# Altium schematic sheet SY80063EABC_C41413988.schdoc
size 127 x 101 mm
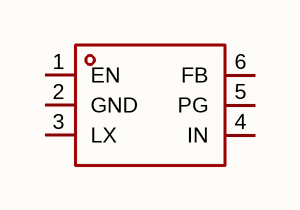
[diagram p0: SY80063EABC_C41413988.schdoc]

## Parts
U?  sy80063eabc_c41413988  [SOT-23-6_L2.9-W1.6-P0.95-LS2.8-BL-1]  (value not drawn)

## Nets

Not connected (* = marked no-connect by the designer): U? 1(EN) 2(GND) 3(LX) 4(IN) 5(PG) 6(FB)

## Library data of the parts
U? = sy80063eabc_c41413988: 功能类型:降压型;工作电压:2.5V~5.5V;输出电压:-;输出电流:3A;输出类型:可调;; Manufacturer: Silergy(矽力杰); AddInBom: yes; ModelId: f68680cba8aa4564861882c5d83eaef7; ModelTransform: 114.173,110.236,0,0,0,0,0,0,0; Function: 降压型; Output Current: 3A; Frequency - Switching: 1MHz; Synchronous Rectifier: 是; Number of Outputs: 1; Topology: 降压式; Switch tube (built-in/external): 内置; Output Type: 可调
